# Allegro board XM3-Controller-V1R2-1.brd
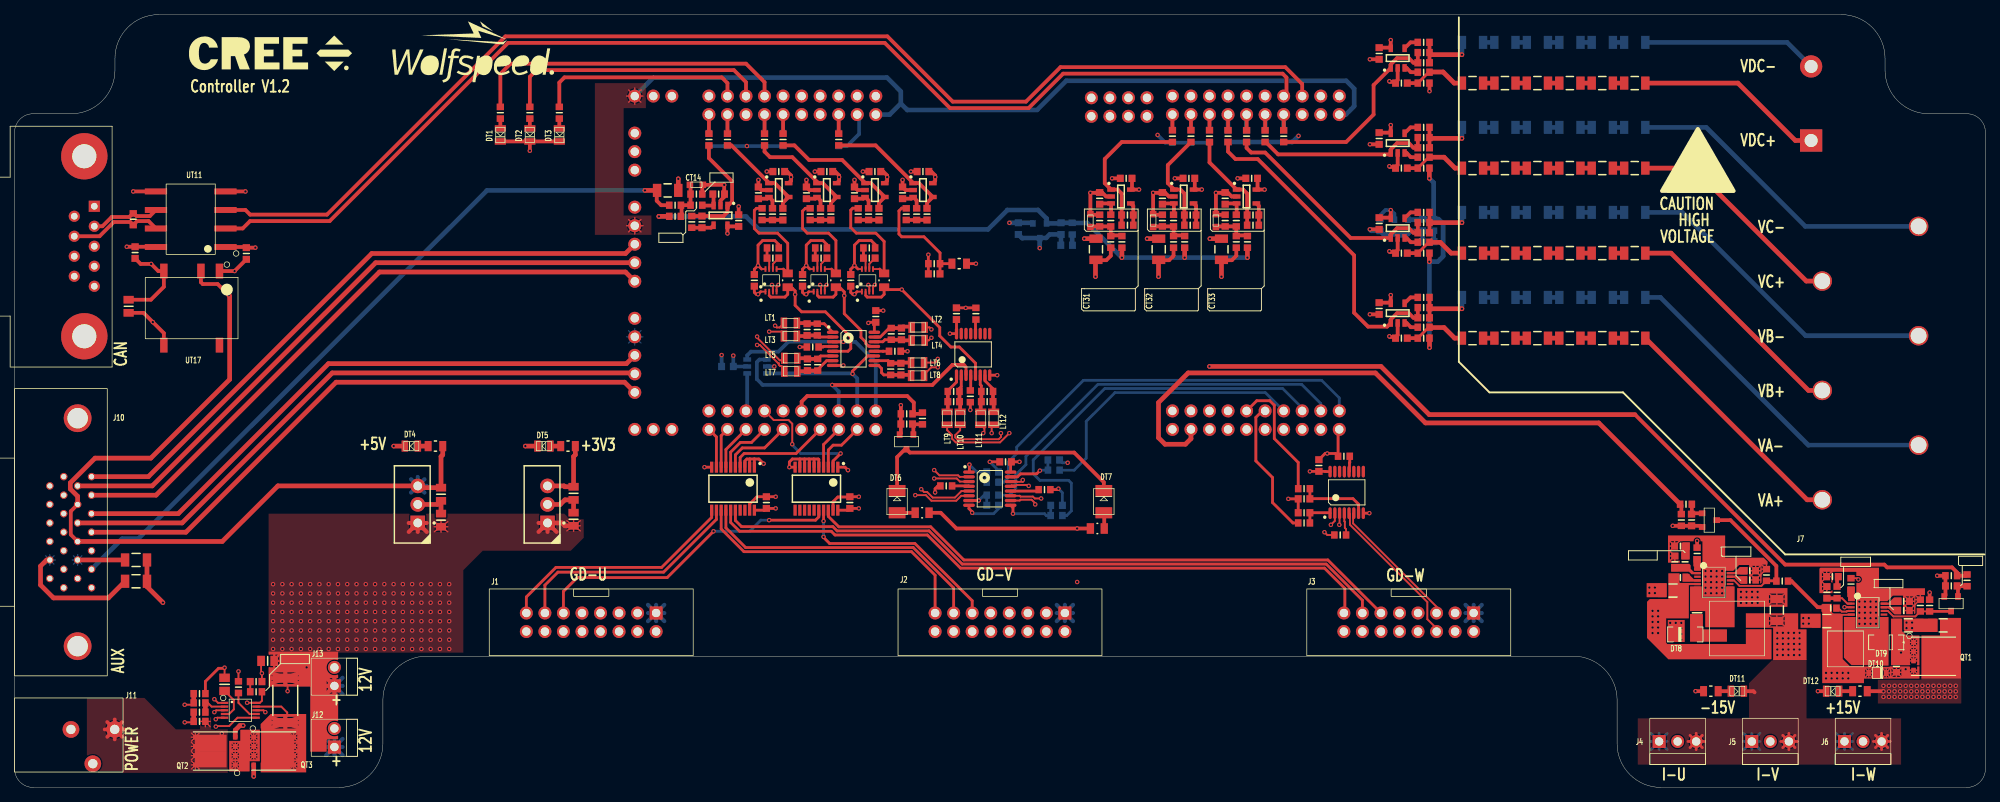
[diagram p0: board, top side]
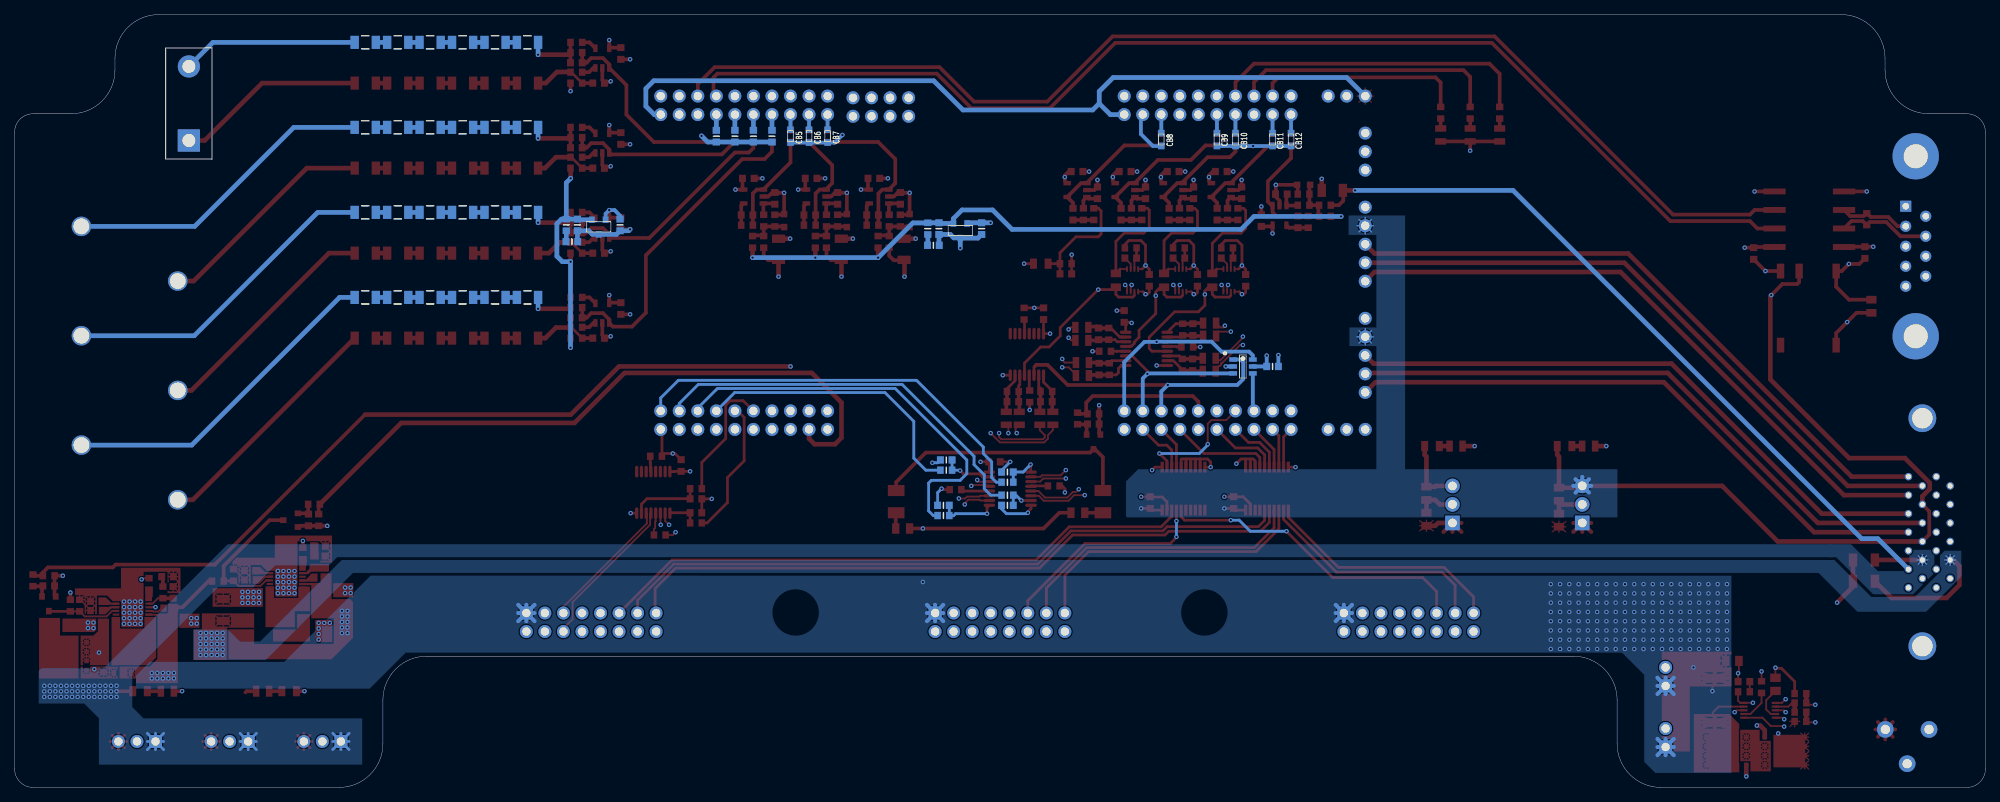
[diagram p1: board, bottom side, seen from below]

Outline 270 x 106 mm; copper layers: TOP, GND1, LAYER3, PWR, GND2, BOTTOM. Coordinates in mm from the lower left corner of the outline.
Outline path: 0,89.86 0,2.54 arc(0.74,0.74) 2.54,0 44.46,0 arc(48.7,1.76) 50.46,6 50.46,12 arc(52.21,16.24) 56.46,18 213.54,18 arc(217.79,16.24) 219.54,12 219.54,6 arc(221.3,1.76) 225.54,0 267.46,0 arc(269.26,0.74) 270,2.54 270,89.86 arc(269.26,91.65) 267.46,92.4 262.25,92.4 arc(258.01,94.15) 256.25,98.4 256.25,100 arc(254.49,104.24) 250.25,106 19.75,106 arc(15.51,104.24) 13.75,100 13.75,98.4 arc(11.99,94.15) 7.75,92.4 2.54,92.4 arc(0.74,91.65) 0,89.86

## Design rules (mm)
constraint set DEFAULT: min track width 0.178
net group A-FAULT-: nets A-FAULT-N A-FAULT-P
net group A-RTD-: nets A-RTD-N A-RTD-P
net group AHS-PWM-: nets AHS-PWM-N AHS-PWM-P
net group ALS-PWM-: nets ALS-PWM-N ALS-PWM-P
net group B-FAULT-: nets B-FAULT-N B-FAULT-P
net group B-RTD-: nets B-RTD-N B-RTD-P
net group BHS-PWM-: nets BHS-PWM-N BHS-PWM-P
net group BLS-PWM-: nets BLS-PWM-N BLS-PWM-P
net group C-FAULT-: nets C-FAULT-N C-FAULT-P
net group C-RTD-: nets C-RTD-N C-RTD-P
net group CANA: nets CANA-H CANA-L
net group CANB: nets CANBH CANBL
net group CHS-PWM-: nets CHS-PWM-N CHS-PWM-P
net group CLS-PWM-: nets CLS-PWM-N CLS-PWM-P
net group VBM: nets N45813 N45817 N45821 N51246 N51250 VB-M

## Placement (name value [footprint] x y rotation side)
CB1  0.27 uF  [CAPC1608X90N]  173.86 89.32 270 bottom
CB2  0.27 uF  [CAPC1608X90N]  171.32 89.32 270 bottom
CB3  0.27 uF  [CAPC1608X90N]  168.78 89.32 270 bottom
CB4  0.27 uF  [CAPC1608X90N]  166.24 89.32 270 bottom
CB5  4700pF  [C_0603]  163.7 89.32 270 bottom
CB6  4700pF  [C_0603]  161.16 89.32 270 bottom
CB7  4700pF  [C_0603]  158.62 89.32 270 bottom
CB8  4700pF  [C_0603]  112.9 88.86 270 bottom
CB9  4700pF  [C_0603]  105.28 88.86 270 bottom
CB10  4700pF  [C_0603]  102.74 88.86 270 bottom
CB11  4700pF  [C_0603]  97.66 88.86 270 bottom
CB12  4700pF  [C_0603]  95.12 88.86 270 bottom
CB13  10000pF  [CAPC1608X90N]  192.89 77.15 270 bottom
CB14  -  [CAPC1608X87N]  187.05 77.15 270 bottom
CB15  10000pF  [CAPC1608X90N]  143.36 76.64 270 bottom
CB16  -  [CAPC1608X87N]  137.52 76.64 270 bottom
CB17  10uF  [CAPC1608X90N]  193.65 74.86 180 bottom
CB18  10uF  [CAPC1608X90N]  144.12 74.35 180 bottom
CB19  -  [CAPC1608X87N]  97.66 57.74 180 bottom
CB20  100pF  [CAPC1608X90N]  142.37 44.91 0 bottom
CB21  100pF  [CAPC1608X90N]  133.98 43.26 0 bottom
CB22  100pF  [CAPC1608X90N]  142.75 38.69 0 bottom
CB23  100pF  [CAPC1608X90N]  133.98 38.69 0 bottom
CT1  -  [CAPC1608X87N]  186.94 100.66 270 top
CT2  4700pF  [CAPC1608X90N]  193.04 99.39 180 top
CT3  4700pF  [CAPC1608X90N]  189.99 96.6 0 top
CT4  -  [CAPC1608X87N]  186.94 89 270 top
CT5  10000pF  [CAPC1608X90N]  193.04 87.73 180 top
CT6  10000pF  [CAPC1608X90N]  189.99 84.94 0 top
CT7  -  [CAPC1608X87N]  104.69 84.47 180 top
CT8  -  [CAPC1608X87N]  111.28 84.47 180 top
CT9  -  [CAPC1608X87N]  117.86 84.47 180 top
CT10  -  [CAPC1608X87N]  124.44 84.47 180 top
CT11  -  [CAPC1608X87N]  152.28 83.53 180 top
CT12  -  [CAPC1608X87N]  160.88 83.53 180 top
CT13  -  [CAPC1608X87N]  169.48 83.53 180 top
CT14  4700pF  [C_0603]  93.41 82.65 0 top
CT15  10000pF  [CAPC1608X90N]  101.9 81.55 270 top
CT16  10000pF  [CAPC1608X90N]  108.48 81.55 270 top
CT17  10000pF  [CAPC1608X90N]  115.07 81.55 270 top
CT18  4700pF  [CAPC1608X90N]  121.65 81.55 270 top
CT19  100pF  [CAPC1608X90N]  96.46 81.38 0 top
CT20  100pF  [CAPC1608X90N]  148.65 80.79 90 top
CT21  100pF  [CAPC1608X90N]  157.25 80.79 90 top
CT22  100pF  [CAPC1608X90N]  165.85 80.79 90 top
CT23  10000pF  [CAPC1608X90N]  105.25 78.63 90 top
CT24  10000pF  [CAPC1608X90N]  111.83 78.63 90 top
CT25  10000pF  [CAPC1608X90N]  118.42 78.63 90 top
CT26  10000pF  [CAPC1608X90N]  125 78.63 90 top
CT27  100pF  [CAPC1608X90N]  152.46 78.51 180 top
CT28  100pF  [CAPC1608X90N]  161.06 78.51 180 top
CT29  100pF  [CAPC1608X90N]  169.66 78.51 180 top
CT30  -  [CAPC1608X87N]  99.2 77.74 90 top
CT31  4700pF  [C_0603]  147.38 77.74 90 top
CT32  4700pF  [C_0603]  155.98 77.74 90 top
CT33  4700pF  [C_0603]  164.58 77.74 90 top
CT34  100pF  [CAPC1608X90N]  94.17 77.57 90 top
CT35  -  [CAPC1608X87N]  186.94 77.34 270 top
CT36  10000pF  [CAPC1608X90N]  193.04 76.07 180 top
CT37  -  [CAPC1608X87N]  16.51 73.36 270 top
CT38  10000pF  [CAPC1608X90N]  189.99 73.28 0 top
CT39  -  [CAPC1608X87N]  31.75 73.23 270 top
CT40  10000pF  [CAPC1608X90N]  103.88 72.6 0 top
CT41  10000pF  [CAPC1608X90N]  110.49 72.6 0 top
CT42  10000pF  [CAPC1608X90N]  117.09 72.6 0 top
CT43  100pF  [CAPC1608X90N]  125.98 70.44 0 top
CT44  -  [CAPC1608X87N]  101.34 69.55 270 top
CT45  -  [CAPC1608X87N]  107.95 69.55 270 top
CT46  -  [CAPC1608X87N]  114.55 69.55 270 top
CT47  10uF  [CAPC2012X135N]  15.62 65.99 90 top
CT48  -  [CAPC1608X87N]  186.94 65.68 270 top
CT49  -  [CAPC1608X87N]  129.03 64.98 90 top
CT50  -  [CAPC1608X87N]  117.98 64.59 90 top
CT51  10000pF  [CAPC1608X90N]  193.04 64.41 180 top
CT52  27pF  [CAPC1608X90N]  108.57 62.8 90 top
CT53  27pF  [CAPC1608X90N]  121.5 62.2 90 top
CT54  10000pF  [CAPC1608X90N]  189.99 61.62 0 top
CT55  27pF  [CAPC1608X90N]  108.62 57.97 270 top
CT56  27pF  [CAPC1608X90N]  121.42 57.38 270 top
CT57  27pF  [CAPC1608X90N]  128.65 52.91 180 top
CT58  27pF  [CAPC1608X90N]  133.24 52.91 0 top
CT59  100pF  [CAPC1608X90N]  122.22 49.84 180 top
CT60  -  [CAPC1608X87N]  135.76 44.66 180 top
CT61  -  [CAPC1608X87N]  178.69 44.15 90 top
CT62  10uF  [CAPC2012X135N]  76.58 40.34 270 top
CT63  10uF  [CAPC2012X135N]  58.42 40.21 270 top
CT64  100pF  [CAPC1608X90N]  176.66 39.58 180 top
CT65  -  [CAPC1608X87N]  103 39.07 90 top
CT66  -  [CAPC1608X87N]  114.43 39.07 90 top
CT67  100pF  [CAPC1608X90N]  176.66 37.67 180 top
CT68  10uF  [CAPC2012X135N]  76.58 36.78 90 top
CT69  100pF  [CAPC1608X90N]  229.74 36.68 270 top
CT70  10uF  [CAPC2012X135N]  58.42 36.65 90 top
CT71  1000pF  [CAPC1608X90N]  228.22 33.1 180 top
CT72  10 uF  [CAPC3216X180N]  16.64 31.19 0 top
CT73  56 pF  [CAPC1608X90N]  227.46 30.94 270 top
CT74  0.1uF  [CAPC1608X90N]  237.72 29.72 180 top
CT75  1000pF  [CAPC1608X90N]  249.05 28.91 180 top
CT76  10 uF  [CAPC3216X180N]  16.64 28.27 0 top
CT77  100pF  [CAPC1608X90N]  265.33 27.64 180 top
CT78  4.7uF  [CAPC3216X180N]  227.2 27 180 top
CT79  56 pF  [CAPC1608X90N]  248.28 26.75 270 top
CT80  0.1uF  [CAPC1608X90N]  258.8 25.53 180 top
CT81  10 uF  [CAPC3216X180N]  241.43 24.34 90 top
CT82  1uF  [CAPC2012X70N]  230.5 23.95 270 top
CT83  4.7uF  [CAPC3216X180N]  248.28 22.81 180 top
CT84  4.7uF  [CAPC3216X180N]  259.43 22.23 0 top
CT85  10 uF  [CAPC3216X180N]  264.21 22.23 180 top
CT86  10uF  [CAPC2012X135N]  34.67 17.35 180 top
CT87  4700pF  [CAPC1608X90N]  33.08 14.51 0 top
CT88  0.022uF  [CAPC2012X70N]  28.76 14.13 90 top
DT1  LH R974-LP-1  [D_0805]  66.55 89.49 270 top
DT2  LTST-C171KSKT  [D_0805]  70.59 89.49 270 top
DT3  LG R971-KN-1  [D_0805]  74.63 89.49 270 top
DT4  LTST-C171GKT  [D_0805]  54.35 46.81 180 top
DT5  LTST-C171GKT  [D_0805]  72.52 46.81 180 top
DT6  AA3528VRVFS/A  [D_1409]  120.9 37.67 90 top
DT7  AA3528VRVFS/A  [D_1409]  149.22 37.67 90 top
DT8  NTS260ESFT3G  [SOD-123F-AC]  228.88 20.98 180 top
DT9  NTS260ESFT3G  [SOD-123F-AC]  256.41 19.89 360 top
DT10  CUS520,H3F  [SOD-323-AC]  255.14 15.7 0 top
DT11  LTST-C171GKT  [D_0805]  236.02 13.2 0 top
DT12  LTST-C171GKT  [D_0805]  249.07 13.2 180 top
J1  SBH11-PBPC-D08-ST-BK  [CON_2X8_SHROUDED_CORRECTED]  87.89 23.92 270 top
J2  SBH11-PBPC-D08-ST-BK  [CON_2X8_SHROUDED_CORRECTED]  143.89 23.92 270 top
J3  SBH11-PBPC-D08-ST-BK  [CON_2X8_SHROUDED_CORRECTED]  199.89 23.92 270 top
J4  0022232031  [CON_1X3_VERT_LOCK]  225.3 6.3 90 top
J5  0022232031  [CON_1X3_VERT_LOCK]  238 6.3 90 top
J6  0022232031  [CON_1X3_VERT_LOCK]  250.7 6.3 90 top
J7  1719231  [PHOENIX_SPT5_6PIN]  247.65 39.45 90 top
J8  CON2  [2POS_400MIL_TERMINAL]  246.12 88.72 90 bottom
J9  A-DS 09 A/KG-T2S  [DB9]  10.92 79.71 90 top
J10  10226-55G3PC  [MDR-26]  6.73 27.38 270 top
J11  PJ-102AH  [POWERJACK-PJ102AH]  13.71 7.95 270 top
J12  640456-2  [CON_1X2_VERT_LOCK]  43.81 5.54 180 top
J13  640456-2  [CON_1X2_VERT_LOCK]  43.81 13.92 180 top
LT1  1uH  [L_0805]  106.29 63.68 0 top
LT2  1uH  [L_0805]  123.79 63.09 180 top
LT3  1uH  [L_0805]  106.29 61.91 0 top
LT4  1uH  [L_0805]  123.79 61.31 180 top
LT5  1uH  [L_0805]  106.34 58.86 0 top
LT6  1uH  [L_0805]  123.71 58.27 180 top
LT7  1uH  [L_0805]  106.34 57.08 0 top
LT8  1uH  [L_0805]  123.71 56.49 180 top
LT9  1uH  [L_0805]  127.76 50.62 90 top
LT10  1uH  [L_0805]  129.54 50.62 90 top
LT11  1uH  [L_0805]  132.35 50.62 90 top
LT12  1uH  [L_0805]  134.13 50.62 90 top
LT13  6.8u  [IND-MSD7342]  235.96 21.8 180 top
LT14  3.3uH  [IND-5040]  250.82 19 0 top
NOREF  -  [unnamed]  19.91 17.77 0 top
NOREF#2  -  [unnamed]  107 23.99 0 top
NOREF#3  -  [#2]  27.62 0 90 top
NOREF#4  -  [#2]  225.42 81.51 0 top
NOREF#5  -  [unnamed]  135 99.7 0 top
NOREF#6  -  [unnamed]  19.91 99.7 0 top
NOREF#7  -  [unnamed]  264 86.4 0 top
NOREF#8  -  [unnamed]  264 6 0 top
NOREF#9  -  [#2]  23.87 96.6 0 top
NOREF#10  -  [unnamed]  163 23.99 0 top
NOREF#11  -  [#2]  0 87.23 0 top
QT1  SI7461DP  [POWER-SO8]  262.89 17.99 0 top
QT2  DMT6005LPS-13  [POWER-SO8]  27.49 4.99 180 top
QT3  DMT6005LPS-13  [POWER-SO8]  35.5 4.99 0 top
RB1  249 kOhm  [RESC3216X65N]  221.96 102.19 180 bottom
RB2  249 kOhm  [RESC3216X65N]  217.51 102.19 180 bottom
RB3  249 kOhm  [RESC3216X65N]  213.07 102.19 180 bottom
RB4  249 kOhm  [RESC3216X65N]  208.62 102.19 180 bottom
RB5  249 kOhm  [RESC3216X65N]  204.18 102.19 180 bottom
RB6  249 kOhm  [RESC3216X65N]  199.73 102.19 180 bottom
RB7  249 kOhm  [RESC3216X65N]  221.96 90.53 180 bottom
RB8  249 kOhm  [RESC3216X65N]  217.51 90.53 180 bottom
RB9  249 kOhm  [RESC3216X65N]  213.07 90.53 180 bottom
RB10  249 kOhm  [RESC3216X65N]  208.62 90.53 180 bottom
RB11  249 kOhm  [RESC3216X65N]  204.18 90.53 180 bottom
RB12  249 kOhm  [RESC3216X65N]  199.73 90.53 180 bottom
RB13  249 kOhm  [RESC3216X65N]  221.96 78.87 180 bottom
RB14  249 kOhm  [RESC3216X65N]  217.51 78.87 180 bottom
RB15  249 kOhm  [RESC3216X65N]  213.07 78.87 180 bottom
RB16  249 kOhm  [RESC3216X65N]  208.62 78.87 180 bottom
RB17  249 kOhm  [RESC3216X65N]  204.18 78.87 180 bottom
RB18  249 kOhm  [RESC3216X65N]  199.73 78.87 180 bottom
RB19  2k  [RESC1608X55N]  194.42 77.15 270 bottom
RB20  2k  [RESC1608X55N]  144.89 76.64 270 bottom
RB21  249 kOhm  [RESC3216X65N]  221.96 67.21 180 bottom
RB22  249 kOhm  [RESC3216X65N]  217.51 67.21 180 bottom
RB23  249 kOhm  [RESC3216X65N]  213.07 67.21 180 bottom
RB24  249 kOhm  [RESC3216X65N]  208.62 67.21 180 bottom
RB25  249 kOhm  [RESC3216X65N]  204.18 67.21 180 bottom
RB26  249 kOhm  [RESC3216X65N]  199.73 67.21 180 bottom
RB27  120  [RESC1608X55N]  142.37 43.51 180 bottom
RB28  120  [RESC1608X55N]  133.98 41.86 180 bottom
RB29  120  [RESC1608X55N]  133.98 40.08 180 bottom
RB30  120  [RESC1608X55N]  142.75 37.29 180 bottom
RT1  4.99k  [RESC1608X55N]  193.04 102.19 180 top
RT2  3.74 k  [RESC1608X55N]  193.04 100.79 180 top
RT3  4.99k  [RESC1608X55N]  193.04 98.1 180 top
RT4  3.74 k  [RESC1608X55N]  193.04 96.6 180 top
RT5  249 kOhm  [RESC3216X65N]  199.73 96.6 180 top
RT6  249 kOhm  [RESC3216X65N]  204.18 96.6 180 top
RT7  249 kOhm  [RESC3216X65N]  208.62 96.6 180 top
RT8  249 kOhm  [RESC3216X65N]  213.07 96.6 180 top
RT9  249 kOhm  [RESC3216X65N]  217.51 96.6 180 top
RT10  249 kOhm  [RESC3216X65N]  221.96 96.6 180 top
RT11  680  [RESC1608X55N]  66.55 92.53 270 top
RT12  680  [RESC1608X55N]  70.59 92.53 270 top
RT13  680  [RESC1608X55N]  74.63 92.53 270 top
RT14  4.99k  [RESC1608X55N]  193.04 90.53 180 top
RT15  49.9  [RESC1608X55N]  158.62 89.32 90 top
RT16  49.9  [RESC1608X55N]  161.16 89.32 90 top
RT17  49.9  [RESC1608X55N]  163.7 89.32 90 top
RT18  49.9  [RESC1608X55N]  166.24 89.32 90 top
RT19  49.9  [RESC1608X55N]  168.78 89.32 90 top
RT20  49.9  [RESC1608X55N]  171.32 89.32 90 top
RT21  49.9  [RESC1608X55N]  173.86 89.32 90 top
RT22  1.8 kOhm  [RESC1608X55N]  193.04 89.13 180 top
RT23  49.9  [RESC1608X55N]  95.12 88.86 90 top
RT24  49.9  [RESC1608X55N]  97.66 88.86 90 top
RT25  49.9  [RESC1608X55N]  102.74 88.86 90 top
RT26  49.9  [RESC1608X55N]  105.28 88.86 90 top
RT27  49.9  [RESC1608X55N]  112.9 88.86 90 top
RT28  4.99k  [RESC1608X55N]  193.04 86.44 180 top
RT29  1.8 kOhm  [RESC1608X55N]  193.04 84.94 180 top
RT30  249 kOhm  [RESC3216X65N]  199.73 84.94 180 top
RT31  249 kOhm  [RESC3216X65N]  204.18 84.94 180 top
RT32  249 kOhm  [RESC3216X65N]  208.62 84.94 180 top
RT33  249 kOhm  [RESC3216X65N]  213.07 84.94 180 top
RT34  249 kOhm  [RESC3216X65N]  217.51 84.94 180 top
RT35  249 kOhm  [RESC3216X65N]  221.96 84.94 180 top
RT36  27  [RESC3216X65N]  89.47 81.88 0 top
RT37  4.02 kOhm  [RESC1608X55N]  93.41 81.38 180 top
RT38  2k  [RESC1608X55N]  90.49 79.85 0 top
RT39  7.15 kOhm  [RESC1608X55N]  93.41 79.85 0 top
RT40  4.99k  [RESC1608X55N]  193.04 78.87 180 top
RT41  30.1k  [RESC1608X55N]  102.41 78.63 270 top
RT42  30.1k  [RESC1608X55N]  103.83 78.63 90 top
RT43  30.1k  [RESC1608X55N]  108.99 78.63 270 top
RT44  30.1k  [RESC1608X55N]  110.41 78.63 90 top
RT45  30.1k  [RESC1608X55N]  115.57 78.63 270 top
RT46  30.1k  [RESC1608X55N]  117 78.63 90 top
RT47  30.1k  [RESC1608X55N]  122.16 78.63 270 top
RT48  17.8k  [RESC1608X55N]  123.58 78.63 90 top
RT49  1.33 k  [RESC1608X55N]  90.49 78.33 0 top
RT50  120  [RESC1608X55N]  16.25 77.93 90 top
RT51  4.02 kOhm  [RESC1608X55N]  148.65 77.74 270 top
RT52  7.15 kOhm  [RESC1608X55N]  150.18 77.74 90 top
RT53  4.02 kOhm  [RESC1608X55N]  157.25 77.74 270 top
RT54  7.15 kOhm  [RESC1608X55N]  158.77 77.74 90 top
RT55  4.02 kOhm  [RESC1608X55N]  165.85 77.74 270 top
RT56  7.15 kOhm  [RESC1608X55N]  167.37 77.74 90 top
RT57  7.87 kOhm  [RESC1608X55N]  92.77 77.57 90 top
RT58  1.8 kOhm  [RESC1608X55N]  193.04 77.47 180 top
RT59  7.87 kOhm  [RESC1608X55N]  152.46 77.11 180 top
RT60  7.87 kOhm  [RESC1608X55N]  161.06 77.11 180 top
RT61  7.87 kOhm  [RESC1608X55N]  169.66 77.11 180 top
RT62  2k  [RESC1608X55N]  150.18 74.82 90 top
RT63  1.33 k  [RESC1608X55N]  151.7 74.82 90 top
RT64  2k  [RESC1608X55N]  158.77 74.82 90 top
RT65  1.33 k  [RESC1608X55N]  160.3 74.82 90 top
RT66  2k  [RESC1608X55N]  167.37 74.82 90 top
RT67  1.33 k  [RESC1608X55N]  168.9 74.82 90 top
RT68  4.99k  [RESC1608X55N]  193.04 74.78 180 top
RT69  2.2k  [RESC1608X55N]  103.88 73.99 180 top
RT70  2.2k  [RESC1608X55N]  110.49 73.99 180 top
RT71  2.2k  [RESC1608X55N]  117.09 73.99 180 top
RT72  27  [RESC3216X65N]  148.14 73.81 90 top
RT73  27  [RESC3216X65N]  156.74 73.81 90 top
RT74  27  [RESC3216X65N]  165.34 73.81 90 top
RT75  1.8 kOhm  [RESC1608X55N]  193.04 73.28 180 top
RT76  249 kOhm  [RESC3216X65N]  199.73 73.28 180 top
RT77  249 kOhm  [RESC3216X65N]  204.18 73.28 180 top
RT78  249 kOhm  [RESC3216X65N]  208.62 73.28 180 top
RT79  249 kOhm  [RESC3216X65N]  213.07 73.28 180 top
RT80  249 kOhm  [RESC3216X65N]  217.51 73.28 180 top
RT81  249 kOhm  [RESC3216X65N]  221.96 73.28 180 top
RT82  10k  [RESC1608X65N]  125.98 71.83 0 top
RT83  10 kOhm  [RESC2012X60N]  129.41 71.83 0 top
RT84  0  [RESC2012X70N]  105.92 69.55 90 top
RT85  0  [RESC2012X70N]  112.52 69.55 90 top
RT86  0  [RESC2012X70N]  119.12 69.55 90 top
RT87  4.99k  [RESC1608X55N]  193.04 67.21 180 top
RT88  1.8 kOhm  [RESC1608X55N]  193.04 65.81 180 top
RT89  15k  [RESC1608X55N]  131.7 64.97 90 top
RT90  4.99k  [RESC1608X55N]  193.04 63.12 180 top
RT91  100  [RESC1608X55N]  109.97 62.8 90 top
RT92  100  [RESC1608X55N]  120.1 62.2 90 top
RT93  1.8 kOhm  [RESC1608X55N]  193.04 61.62 180 top
RT94  249 kOhm  [RESC3216X65N]  199.73 61.62 180 top
RT95  249 kOhm  [RESC3216X65N]  204.18 61.62 180 top
RT96  249 kOhm  [RESC3216X65N]  208.62 61.62 180 top
RT97  249 kOhm  [RESC3216X65N]  213.07 61.62 180 top
RT98  249 kOhm  [RESC3216X65N]  217.51 61.62 180 top
RT99  249 kOhm  [RESC3216X65N]  221.96 61.62 180 top
RT100  15k  [RESC1608X55N]  109.35 60.4 0 top
RT101  15k  [RESC1608X55N]  120.6 59.82 0 top
RT102  100  [RESC1608X55N]  110.02 57.97 270 top
RT103  100  [RESC1608X55N]  120.03 57.38 270 top
RT104  100  [RESC1608X55N]  128.65 54.31 180 top
RT105  100  [RESC1608X55N]  133.24 54.31 0 top
RT106  15k  [RESC1608X55N]  130.94 53.64 90 top
RT107  10k  [RESC1608X65N]  122.22 51.24 180 top
RT108  120  [RESC1608X55N]  124.38 50.6 270 top
RT109  499  [RESC2012X60N]  57.66 46.81 180 top
RT110  249  [RESC2012X60N]  75.82 46.81 180 top
RT111  15k  [RESC1608X55N]  182.12 45.42 0 top
RT112  15k  [RESC1608X55N]  127.63 41.35 0 top
RT113  120  [RESC1608X55N]  176.66 40.97 0 top
RT114  15k  [RESC1608X55N]  141.1 40.85 180 top
RT115  120  [RESC1608X55N]  228.98 38.84 0 top
RT116  1.8k  [RESC2013X65N]  124.33 37.67 180 top
RT117  10k  [RESC1608X65N]  228.34 36.68 270 top
RT118  120  [RESC1608X55N]  176.66 36.27 0 top
RT119  1.8k  [RESC2013X65N]  148.33 35.51 0 top
RT120  15k  [RESC1608X55N]  181.61 34.62 0 top
RT121  180K  [RESC1608X55N]  230.5 32.08 90 top
RT122  10k  [RESC1608X65N]  228.85 30.94 90 top
RT123  10k  [RESC1608X65N]  240 29.14 90 top
RT124  10k  [RESC1608X65N]  265.33 29.03 180 top
RT125  100k  [RESC1608X55N]  228.22 28.78 0 top
RT126  45.3k  [RESC1608X55N]  237.72 28.45 180 top
RT127  120  [RESC1608X55N]  267.49 28.4 270 top
RT128  56k  [RESC1608X55N]  242.16 28.3 0 top
RT129  165k  [RESC1608X55N]  251.59 27.89 90 top
RT130  10k  [RESC1608X65N]  249.68 26.75 90 top
RT131  10k  [RESC1608X65N]  261.09 24.95 90 top
RT132  56k  [RESC1608X55N]  262.36 24.95 90 top
RT133  100k  [RESC1608X55N]  248.79 24.59 0 top
RT134  45.3k  [RESC1608X55N]  258.8 24.26 180 top
RT135  100k  [RESC1608X55N]  257.81 16.59 270 top
RT136  100k  [RESC1608X55N]  30.67 13.75 270 top
RT137  2.43k  [RESC2012X60N]  232.39 13.2 0 top
RT138  2.43k  [RESC2012X60N]  252.81 13.2 180 top
RT139  22k  [RESC1608X55N]  33.08 13.12 0 top
RT140  200k  [RESC1608X55N]  25.34 12.86 0 top
RT141  0.01  [RESC6432X70N]  37.08 11.93 90 top
RT142  100k  [RESC1608X55N]  25.34 11.59 180 top
RT143  2.7 M  [RESC1608X55N]  25.34 10.32 0 top
RT144  2.7 M  [RESC1608X55N]  25.34 9.05 180 top
UB1  ISL21080CIH315Z-TK  [SOT_23_3]  192.36 74.99 180 bottom
UB2  ISL21080CIH330Z-TK  [SOT_23_3]  142.83 74.48 180 bottom
UB3  SN74LVC1G11DBVR  [SOT_23_6]  103.06 58.69 270 bottom
UT1  AD8615AUJZ-REEL7  [SOT23-5_0_95X2_70P_H1_22]  189.48 100.03 90 top
UT2  AD8615AUJZ-REEL7  [SOT23-5_0_95X2_70P_H1_22]  189.48 88.37 90 top
UT3  AD8615AUJZ-REEL7  [SOT23-5_0_95X2_70P_H1_22]  104.69 81.93 0 top
UT4  AD8615AUJZ-REEL7  [SOT23-5_0_95X2_70P_H1_22]  111.28 81.93 0 top
UT5  AD8615AUJZ-REEL7  [SOT23-5_0_95X2_70P_H1_22]  117.86 81.93 0 top
UT6  AD8615AUJZ-REEL7  [SOT23-5_0_95X2_70P_H1_22]  124.44 81.93 0 top
UT7  AD8615AUJZ-REEL7  [SOT23-5_0_95X2_70P_H1_22]  151.57 81.05 0 top
UT8  AD8615AUJZ-REEL7  [SOT23-5_0_95X2_70P_H1_22]  160.17 81.05 0 top
UT9  AD8615AUJZ-REEL7  [SOT23-5_0_95X2_70P_H1_22]  168.77 81.05 0 top
UT10  AD8615AUJZ-REEL7  [SOT23-5_0_95X2_70P_H1_22]  96.71 78.45 270 top
UT11  ISO1050DUBR  [SMD-8_GULL_WING_V2]  28.89 74.12 180 top
UT12  AD8615AUJZ-REEL7  [SOT23-5_0_95X2_70P_H1_22]  189.48 76.71 90 top
UT13  F28379D-launchpad  [F28379D-LAUNCHPAD-1]  84.96 79.58 180 top
UT14  74LVC123  [VFSOP-8]  103.63 69.55 90 top
UT15  74LVC123  [VFSOP-8]  110.23 69.55 90 top
UT16  74LVC123  [VFSOP-8]  116.84 69.55 90 top
UT17  R1SE-0505-R  [8-SMD-5LEADS]  28.07 70.82 270 top
UT18  AD8615AUJZ-REEL7  [SOT23-5_0_95X2_70P_H1_22]  189.48 65.05 90 top
UT19  AM26LV32EIPWR  [TSSOP-16P_P65MM]  114.93 60.15 0 top
UT20  AM26LV32EIPWR  [TSSOP-16P_P65MM]  131.32 59.39 90 top
UT21  BSS138L  [SOT_23_3]  119.8 45.52 0 top
UT22  SN74LV541ATPWR  [SOP65P640X120-20AN]  98.42 40.97 270 top
UT23  SN74LV541ATPWR  [SOP65P640X120-20AN]  109.85 40.97 270 top
UT24  AM26LV31EIPWR  [TSSOP-16P_P65MM]  133.6 40.97 0 top
UT25  AM26LV31EIPWR  [TSSOP-16P_P65MM]  182.5 40.46 90 top
UT26  R-78E5.0-1.0  [TO-220V]  55.23 38.81 90 top
UT27  R-78E3.3-1.0  [TO-220V]  73.01 38.81 90 top
UT28  BSS138L  [SOT_23_3]  234.06 34.27 90 top
UT29  LT3581  [MSOP-16-EP]  232.79 28.15 0 top
UT30  BSS138L  [SOT_23_3]  262.91 23.32 0 top
UT31  LT3581  [MSOP-16-EP]  253.87 23.95 0 top
UT32  LTC4368IMS-2#PBF  [MSOP_10]  28.76 11.59 0 top

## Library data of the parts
CB1-CB13 CB15 CB17 CB18 CB20-CB23 CT2 CT3 CT5 CT6 CT14-CT29 CT31-CT34 CT36 CT38 CT40-CT43 CT47 CT51-CT59 CT62-CT64 CT67-CT88 = CAP
CB14 CB16 CB19 CT1 CT4 CT7-CT13 CT30 CT35 CT37 CT39 CT44-CT46 CT48-CT50 CT60 CT61 CT65 CT66 = CAP_CAPC1608X87N_DISCRETE_0.1UF
DT1-DT5 DT11 DT12 = LED_0
DT6 DT7 = LED - Purple
DT8 DT9 = DIODE_SCHOTTKY_0
DT10 = DIODE_SCHOTTKY_C2_A1_0
J1-J3 = CON16A_Corrected
J4-J6 = CON3
J7 = HDR_1X6_M
J8 = CON2
J9 = DSUB - NI CAN Interface_0: User Part Number: TMP-1302
J10 = CONN CENT RCPT 26
J11 = power_jack
J12 J13 = 1x2 100mil
LT1-LT12 = INDUCTOR
LT13 = Coupled_Inductor
LT14 = IND
QT1 = MOSFET_P_PSO8: User Part Number: TMP-1595; Tolerance: TOL
QT2 QT3 = MOSFET_N_PSO8: User Part Number: TMP-1530; Tolerance: TOL
RB1-RB26 RT1-RT36 RT38 RT40-RT48 RT58 RT62 RT64 RT66 RT68-RT81 RT84-RT88 RT90-RT99 RT102-RT105 RT126 RT129 RT134 RT141 = RES
RB27-RB30 RT37 RT39 RT49-RT57 RT59-RT61 RT63 RT65 RT67 RT82 RT89 RT100 RT101 RT106-RT125 RT127 RT128 RT130-RT133 RT135-RT140 RT142-RT144 = R
RT83 = PTC
UB1 UB2 = REF3312AIDCKR - Vref_0
UB3 = AND3_1X_6PIN
UT1-UT10 UT12 UT18 = AD8615
UT11 = ISO1050DUB
UT13 = F28379D-launchpad
UT14-UT16 = 74LVC123
UT17 = R1se-0505-R
UT19 UT20 = DIFFRCVR_4XG_16P
UT21 UT28 UT30 = MOSFET_N_GSD
UT22 UT23 = 74-541_20P
UT24 UT25 = DIFFDRVR_4X_16P
UT26 UT27 = LM7805
UT29 UT31 = LT3581
UT32 = LTC4368

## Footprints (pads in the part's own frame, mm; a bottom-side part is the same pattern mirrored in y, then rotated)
2POS_400MIL_TERMINAL
  rect 3.048x3.048 hole 1.778: 1(0,0)
  round 3.048 hole 1.778: 2(10.16,0)
8-SMD-5LEADS
  rect 2.032x1.016 smd: 1(0,0) 2(0,-2.54) 4(0,-7.62) 5(10.16,-7.62) 8(10.16,0)
C_0603
  rect 0.889x0.889 smd: 1(-0.889,0) 2(0.889,0)
CAPC1608X87N
  rect 0.95x1 smd: 1(-0.8,0) 2(0.8,0)
CAPC1608X90N
  rect 0.95x1 smd: 1(-0.8,0) 2(0.8,0)
CAPC2012X70N
  rect 1.15x1.45 smd: 1(-0.9,0) 2(0.9,0)
CAPC2012X135N
  rect 1.05x1.4 smd: 1(-0.9,0) 2(0.9,0)
CAPC3216X180N
  rect 1.15x1.8 smd: 1(-1.5,0) 2(1.5,0)
CON_1X2_VERT_LOCK
  rect 1.778x1.778 hole 1.143: 1(0,0)
  round 1.778 hole 1.143: 2(0,-2.54)
CON_1X3_VERT_LOCK
  rect 1.778x1.778 hole 1.143: 1(0,0)
  round 1.778 hole 1.143: 2(0,-2.54) 3(0,-5.08)
CON_2X8_SHROUDED_CORRECTED
  rect 1.778x1.778 hole 1.143: 1(0,0)
  round 1.778 hole 1.143: 2(2.54,0) 3(0,-2.54) 4(2.54,-2.54) 5(0,-5.08) 6(2.54,-5.08) 7(0,-7.62) 8(2.54,-7.62) 9(0,-10.16) 10(2.54,-10.16) 11(0,-12.7) 12(2.54,-12.7) 13(0,-15.24) 14(2.54,-15.24) 15(0,-17.78) 16(2.54,-17.78)
D_0805
  rect 0.889x1.524 smd: 1(-0.889,0) 2(0.889,0)
D_1409
  rect 1.524x2.286 smd: 1(0,0) 2(3.048,0)
DB9
  rect 1.524x1.524 hole 0.914: 1(0,0)
  round 1.524 hole 0.914: 2(-2.743,0) 3(-5.486,0) 4(-8.23,0) 5(-10.973,0) 6(-1.372,2.743) 7(-4.115,2.743) 8(-6.858,2.743) 9(-9.601,2.743)
  round 6.35 hole 3.302: 10(6.858,1.372) 11(-17.831,1.372)
F28379D-LAUNCHPAD-1
  round 1.778 hole 1.143: 1(-96.52,-15.24) 2(-93.98,-15.24) 3(-91.44,-15.24) 4(-88.9,-15.24) 5(-86.36,-15.24) 6(-83.82,-15.24) 7(-81.28,-15.24) 8(-78.74,-15.24) 9(-76.2,-15.24) 10(-73.66,-15.24) 11(-73.66,30.48) 12(-76.2,30.48) 13(-78.74,30.48) 14(-81.28,30.48) 15(-83.82,30.48) 16(-86.36,30.48) 17(-88.9,30.48) 18(-91.44,30.48) 19(-93.98,30.48) 20(-96.52,30.48) 21(-96.52,-12.7) 22(-93.98,-12.7) 23(-91.44,-12.7) 24(-88.9,-12.7) 25(-86.36,-12.7) 26(-83.82,-12.7) 27(-81.28,-12.7) 28(-78.74,-12.7) 29(-76.2,-12.7) 30(-73.66,-12.7) 31(-73.66,27.94) 32(-76.2,27.94) 33(-78.74,27.94) 34(-81.28,27.94) 35(-83.82,27.94) 36(-86.36,27.94) 37(-88.9,27.94) 38(-91.44,27.94) 39(-93.98,27.94) 40(-96.52,27.94) 41(-33.02,-15.24) 42(-30.48,-15.24) 43(-27.94,-15.24) 44(-25.4,-15.24) 45(-22.86,-15.24) 46(-20.32,-15.24) 47(-17.78,-15.24) 48(-15.24,-15.24) 49(-12.7,-15.24) 50(-10.16,-15.24) 51(-10.16,30.48) 52(-12.7,30.48) 53(-15.24,30.48) 54(-17.78,30.48) 55(-20.32,30.48) 56(-22.86,30.48) 57(-25.4,30.48) 58(-27.94,30.48) 59(-30.48,30.48) 60(-33.02,30.48) 61(-33.02,-12.7) 62(-30.48,-12.7) 63(-27.94,-12.7) 64(-25.4,-12.7) 65(-22.86,-12.7) 66(-20.32,-12.7) 67(-17.78,-12.7) 68(-15.24,-12.7) 69(-12.7,-12.7) 70(-10.16,-12.7) 71(-10.16,27.94) 72(-12.7,27.94) 73(-15.24,27.94) 74(-17.78,27.94) 75(-20.32,27.94) 76(-22.86,27.94) 77(-25.4,27.94) 78(-27.94,27.94) 79(-30.48,27.94) 80(-33.02,27.94) 81(-70.176,-12.466) 82(-70.176,-15.006) 83(-67.636,-12.466) 84(-67.636,-15.006) 85(-65.096,-12.466) 86(-65.096,-15.006) 87(-62.556,-12.466) 88(-62.556,-15.006) 89(0,25.4) 90(0,22.86) 91(0,20.32) 92(0,17.78) 93(0,15.24) 94(0,10.16) 95(0,7.62) 96(0,5.08) 97(0,2.54) 98(0,0) 99(0,-5.08) 100(0,-7.62) 101(0,-10.16) 102(0,30.48) 103(-2.54,30.48) 104(-5.08,30.48) 105(0,-15.24) 106(-2.54,-15.24) 107(-5.08,-15.24)
IND-5040
  rect 1.5x4 smd: 1(-1.8,0) 2(1.8,0)
IND-MSD7342
  rect 2.35x1.1 smd: 1(-2.825,0.85) 2(-2.825,-0.85) 3(2.825,-0.85) 4(2.825,0.85)
L_0805
  rect 0.889x1.524 smd: 1(-0.889,0) 2(0.889,0)
MDR-26
  round 3.81 hole 2.794: (-23.254,1.905) (8.014,1.905)
  round 1.016 hole 0.711: 1(0,0) 2(0,3.81) 3(-1.27,-1.905) 4(-1.27,1.905) 5(-2.54,0) 6(-2.54,3.81) 7(-3.81,-1.905) 8(-3.81,1.905) 9(-5.08,0) 10(-5.08,3.81) 11(-6.35,-1.905) 12(-6.35,1.905) 13(-7.62,0) 14(-7.62,3.81) 15(-8.89,-1.905) 16(-8.89,1.905) 17(-10.16,0) 18(-10.16,3.81) 19(-11.43,-1.905) 20(-11.43,1.905) 21(-12.7,0) 22(-12.7,3.81) 23(-13.97,-1.905) 24(-13.97,1.905) 25(-15.24,0) 26(-15.24,3.81)
MSOP-16-EP
  rect 0.9x0.3 smd: 1(-2.235,1.751) 2(-2.235,1.251) 3(-2.235,0.751) 4(-2.235,0.25) 5(-2.235,-0.25) 6(-2.235,-0.751) 7(-2.235,-1.251) 8(-2.235,-1.751) 9(2.235,-1.751) 10(2.235,-1.251) 11(2.235,-0.751) 12(2.235,-0.25) 13(2.235,0.25) 14(2.235,0.751) 15(2.235,1.251) 16(2.235,1.751)
  rect 1.651x3.048 smd: 17(0,0)
MSOP_10
  rect 1.016x0.305 smd: 1(0,0) 2(0,-0.508) 3(0,-1.016) 4(0,-1.524) 5(0,-2.032) 6(4.318,-2.032) 7(4.318,-1.524) 8(4.318,-1.016) 9(4.318,-0.508) 10(4.318,0)
PHOENIX_SPT5_6PIN
  round 2.667 hole 2.159: 1(0,0) 2(7.5,-13.2) 3(15,0) 4(22.5,-13.2) 5(30,0) 6(37.5,-13.2)
POWER-SO8
  rect 0.63x0.65 smd: 1(-2.735,1.905) 2(-2.735,0.635) 3(-2.735,-0.635) 4(-2.735,-1.905) 5(2.735,-1.905) 6(2.735,-0.635) 7(2.735,0.635) 8(2.735,1.905)
POWERJACK-PJ102AH
  round 2.286 hole 1.27: 1(0,0) 2(0,-5.994) 3(4.699,-2.997)
RESC1608X55N
  rect 0.9x1 smd: 1(-0.8,0) 2(0.8,0)
RESC1608X65N
  rect 0.9x1 smd: 1(-0.8,0) 2(0.8,0)
RESC2012X60N
  rect 0.95x1.4 smd: 1(-1,0) 2(1,0)
RESC2012X70N
  rect 1.05x1.4 smd: 1(-0.95,0) 2(0.95,0)
RESC2013X65N
  rect 1x1.45 smd: 1(-0.95,0) 2(0.95,0)
RESC3216X65N
  rect 1.15x1.8 smd: 1(-1.45,0) 2(1.45,0)
RESC6432X70N
  rect 1.25x3.4 smd: 1(-3.05,0) 2(3.05,0)
SMD-8_GULL_WING_V2
  rect 3.048x0.813 smd: 1(0,0) 2(0,-2.54) 3(0,-5.08) 4(0,-7.62) 5(9.525,-7.62) 6(9.525,-5.08) 7(9.525,-2.54) 8(9.525,0)
SOD-123F-AC
  rect 0.914x1.27 smd: 1(1.651,0) 2(-1.651,0)
SOD-323-AC
  rect 0.635x0.838 smd: A(-1.118,0) C(1.27,0)
SOP65P640X120-20AN
  rect 1.5x0.45 smd: 1(-2.95,2.925) 2(-2.95,2.275) 3(-2.95,1.625) 4(-2.95,0.975) 5(-2.95,0.325) 6(-2.95,-0.325) 7(-2.95,-0.975) 8(-2.95,-1.625) 9(-2.95,-2.275) 10(-2.95,-2.925) 11(2.95,-2.925) 12(2.95,-2.275) 13(2.95,-1.625) 14(2.95,-0.975) 15(2.95,-0.325) 16(2.95,0.325) 17(2.95,0.975) 18(2.95,1.625) 19(2.95,2.275) 20(2.95,2.925)
SOT23-5_0_95X2_70P_H1_22
  rect 1.05x0.6 smd: 1(-1.35,0.95) 2(-1.35,0) 3(-1.35,-0.95) 4(1.35,-0.95) 5(1.35,0.95)
SOT_23_3
  rect 0.787x0.889 smd: 1(3.327,2.87) 2(1.448,2.87) 3(2.388,0.864)
SOT_23_6
  rect 0.61x1.067 smd: 1(0,0) 2(0.953,0) 3(1.905,0) 4(1.905,2.692) 5(0.953,2.692) 6(0,2.692)
TO-220V
  rect 2x2 hole 1.2: 1(-2.54,0)
  round 2 hole 1.2: 2(0,0) 3(2.54,0)
TSSOP-16P_P65MM
  oval 1.6x0.45 smd: 1(-2.85,2.275) 2(-2.85,1.625) 3(-2.85,0.975) 4(-2.85,0.325) 5(-2.85,-0.325) 6(-2.85,-0.975) 7(-2.85,-1.625) 8(-2.85,-2.275) 9(2.85,-2.275) 10(2.85,-1.625) 11(2.85,-0.975) 12(2.85,-0.325) 13(2.85,0.325) 14(2.85,0.975) 15(2.85,1.625) 16(2.85,2.275)
unnamed
  round 0 hole 4.318 unplated: (0,0)
VFSOP-8
  rect 0.762x0.254 smd: 1(-1.549,0.762) 2(-1.549,0.254) 3(-1.549,-0.254) 4(-1.549,-0.762) 5(1.549,-0.762) 6(1.549,-0.254) 7(1.549,0.254) 8(1.549,0.762)

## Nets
+1V5REF: CB13.1 RB19.1 RT29.1 RT75.1 RT93.1 UB1.2(OUT)
+3V3: CB14.1 CB16.1 CB19.1 CT1.1 CT4.1 CT7.1 CT8.1 CT9.1 CT10.1 CT11.1 CT12.1 CT13.1 CT30.1 CT35.1 CT39.1 CT44.1 CT45.1 CT46.1 CT48.1 CT49.1 CT50.1 CT60.1 CT61.1 CT62.1 J10.10 RT69.1 RT70.1 RT71.1 RT83.2 RT100.1 RT106.1 RT110.1 RT112.1 RT120.1 UB1.1 UB2.1 UB3.5 UT1.5 UT2.5 UT3.5 UT4.5 UT5.5 UT6.5 UT7.5 UT8.5 UT9.5 UT10.5 UT11.1 UT12.5 UT13.1 UT13.41 UT13.102 UT14.3 UT14.8(VCC) UT15.3 UT15.8(VCC) UT16.3 UT16.8(VCC) UT18.5 UT19.16 UT20.16 UT24.16 UT25.16 UT27.3(OUTPUT)
+3VREF: CB15.1 RB20.1 RT49.1 RT63.1 RT65.1 RT67.1 UB2.2(OUT)
+5V: CT63.1 CT65.1 CT66.1 J10.12 J10.20 RT109.1 UT13.21 UT13.61 UT13.92 UT13.97 UT13.105 UT17.2 UT22.20 UT23.20 UT26.3(OUTPUT)
+5V-ISO: CT37.1 CT47.1 J9.9 UT11.8(VCC2) UT17.5
+12V: CT68.1 CT70.1 CT78.1 CT83.1 CT86.1 DT10.A J1.1 J2.1 J3.1 J12.1 J13.1 LT13.1 LT14.1 RT116.1 RT119.1 RT125.1 RT128.2 RT132.2 RT133.1 RT141.2 UT26.1 UT27.1 UT29.5 UT31.5 UT32.8(VOUT)
+15V: CT72.1 CT85.1 J4.1 J5.1 J6.1 J10.8 QT1.5 QT1.6 QT1.7 QT1.8 RT138.1
-15V: CT76.1 CT81.1 DT11.2(C) J4.3 J5.3 J6.3 J10.7 LT13.2 RT121.2
VIN: J11.1(VIN) QT2.5 QT2.6 QT2.7 QT2.8 RT136.1 RT144.1 UT32.1
0: CB1.2 CB2.2 CB3.2 CB4.2 CB5.2 CB6.2 CB7.2 CB8.2 CB9.2 CB10.2 CB11.2 CB12.2 CB13.2 CB14.2 CB15.2 CB16.2 CB17.2 CB18.2 CB19.2 CB20.2 CB21.2 CB22.2 CB23.2 CT1.2 CT3.1 CT4.2 CT6.1 CT7.2 CT8.2 CT9.2 CT10.2 CT11.2 CT12.2 CT13.2 CT14.2 CT15.1 CT16.1 CT17.1 CT18.1 CT19.2 CT20.2 CT21.2 CT22.2 CT30.2 CT31.2 CT32.2 CT33.2 CT35.2 CT38.1 CT39.2 CT43.1 CT44.2 CT45.2 CT46.2 CT48.2 CT49.2 CT50.2 CT54.1 CT59.2 CT60.2 CT61.2 CT62.2 CT63.2 CT64.2 CT65.2 CT66.2 CT67.2 CT68.2 CT69.2 CT70.2 CT71.2 CT72.2 CT73.1 CT74.1 CT75.2 CT76.2 CT77.2 CT78.2 CT79.1 CT80.1 CT81.2 CT83.2 CT84.2 CT85.2 CT86.2 CT87.2 CT88.2 DT1.2(C) DT2.2(C) DT3.2(C) DT4.2(C) DT5.2(C) DT8.1(C) DT12.2(C) J1.2 J1.12 J1.14 J1.16 J2.2 J2.12 J2.14 J2.16 J3.2 J3.12 J3.14 J3.16 J10.3 J10.4 J10.5 J10.9 J10.11 J10.13 J10.15 J10.17 J10.19 J10.21 J10.23 J10.25 J11.2 J11.3 J12.2 J13.2 RT4.1 RT36.2 RT37.1 RT51.1 RT53.1 RT55.1 RT72.2 RT73.2 RT74.2 RT82.1 RT89.2 RT101.2 RT107.2 RT111.1 RT114.1 RT117.2 RT123.2 RT124.2 RT126.1 RT131.2 RT134.1 RT137.1 RT140.2 UB1.3 UB2.3 UB3.2 UT1.2(V-) UT2.2(V-) UT3.2(V-) UT4.2(V-) UT5.2(V-) UT6.2(V-) UT7.2(V-) UT8.2(V-) UT9.2(V-) UT10.2(V-) UT11.4 UT12.2(V-) UT13.20 UT13.22 UT13.60 UT13.62 UT13.82 UT13.84 UT13.86 UT13.88 UT13.93 UT13.98 UT13.101 UT13.103 UT13.104 UT13.106 UT13.107(GND15) UT14.1 UT14.4 UT15.1 UT15.4 UT16.1 UT16.4 UT17.1 UT18.2(V-) UT19.8 UT20.8 UT21.2(S) UT22.1 UT22.2 UT22.3 UT22.10 UT22.19 UT23.1 UT23.5 UT23.6 UT23.7 UT23.8 UT23.9 UT23.10 UT23.19 UT24.8 UT25.8 UT26.2 UT27.2 UT28.2(S) UT29.16 UT29.17 UT30.2(S) UT31.16 UT31.17 UT32.5
1: CT37.2 CT47.2 J9.3(V-) J9.5 J9.10 J9.11 UT11.5 UT17.4
A-CURRENT: CB7.1 RT15.2 UT13.30
A-FAULT: UB3.6 UT13.80 UT19.3
A-FAULT-N: J1.8 LT1.1
A-FAULT-N-FILTER: CT52.2 LT1.2 RT91.2 UT19.1
A-FAULT-P: J1.7 LT3.1
A-FAULT-P-FILTER: CT52.1 LT3.2 RT91.1 UT19.2
A-LEN: J1.13 UT22.12
A-LEN-OUT: UT13.52 UT22.8
A-OCEN: J1.15 UT22.11(Y8)
A-OCEN-OUT: UT13.51 UT22.9
A-PSDIS: J1.11 UT23.16
A-PSDIS-OUT: UT13.58 UT23.4
A-RTD: RT84.1 UT13.46 UT14.2 UT19.5
A-RTD-N: J1.10 LT7.1
A-RTD-N-FILTER: CT55.2 LT7.2 RT102.2 UT19.7
A-RTD-P: J1.9 LT5.1
A-RTD-P-FILTER: CT55.1 LT5.2 RT102.1 UT19.6
A-TEMP: CB11.1 RT24.2 UT13.69
AHS-PWM: RB28.1 UT13.40
AHS-PWM-N: J1.4 UT24.3
AHS-PWM-P: J1.3 UT24.2
ALS-PWM: RB29.1 UT13.39
ALS-PWM-N: J1.6 UT24.5
ALS-PWM-P: J1.5 UT24.6
B-CURRENT: CB6.1 RT16.2 UT13.29
B-FAULT: UB3.3 UT13.79 UT19.11
B-FAULT-N: J2.8 LT8.1
B-FAULT-N-FILTER: CT56.2 LT8.2 RT103.2 UT19.9
B-FAULT-P: J2.7 LT6.1
B-FAULT-P-FILTER: CT56.1 LT6.2 RT103.1 UT19.10
B-LEN: J2.13 UT22.14
B-LEN-OUT: UT13.54 UT22.6
B-OCEN: J2.15 UT22.13
B-OCEN-OUT: UT13.53 UT22.7
B-PSDIS: J2.11 UT23.17
B-PSDIS-OUT: UT13.59 UT23.3
B-RTD: RT85.1 UT13.45 UT15.2 UT19.13(Y4)
B-RTD-N: J2.10 LT2.1
B-RTD-N-FILTER: CT53.2 LT2.2 RT92.2 UT19.15
B-RTD-P: J2.9 LT4.1
B-RTD-P-FILTER: CT53.1 LT4.2 RT92.1 UT19.14
B-TEMP: CB10.1 RT25.2 UT13.67
BHS-PWM: RB30.1 UT13.38
BHS-PWM-N: J2.4 UT24.11
BHS-PWM-P: J2.3 UT24.10
BLS-PWM: RB27.1 UT13.37
BLS-PWM-N: J2.6 UT24.13(Z4)
BLS-PWM-P: J2.5 UT24.14
C-CURRENT: CB5.1 RT17.2 UT13.28
C-FAULT: UB3.1 UT13.78 UT20.3
C-FAULT-N: J3.8 LT9.1
C-FAULT-N-FILTER: CT57.2 LT9.2 RT104.2 UT20.1
C-FAULT-P: J3.7 LT10.1
C-FAULT-P-FILTER: CT57.1 LT10.2 RT104.1 UT20.2
C-LEN: J3.13 UT22.16
C-LEN-OUT: UT13.57 UT22.4
C-OCEN: J3.15 UT22.15
C-OCEN-OUT: UT13.55 UT22.5
C-PSDIS: J3.11 UT23.18
C-PSDIS-OUT: UT13.74 UT23.2
C-RTD: RT86.1 UT13.42 UT16.2 UT20.5
C-RTD-N: J3.10 LT12.1
C-RTD-N-FILTER: CT58.2 LT12.2 RT105.2 UT20.7
C-RTD-P: J3.9 LT11.1
C-RTD-P-FILTER: CT58.1 LT11.2 RT105.1 UT20.6
C-TEMP: CB9.1 RT26.2 UT13.66
CANA-H: J9.7 RT50.1 UT11.7
CANA-L: J9.2 RT50.2 UT11.6
CANA-RX: UT11.2 UT13.4
CANA-TX: UT11.3 UT13.3
CANBH: J10.2 UT13.99
CANBL: J10.1 UT13.100
CASE-LED1: RT107.1 RT108.1 UT13.76
CASE-LED2: UT13.75
CASE-TEMP: CB8.1 RT27.2 UT13.63
CHS-PWM: RT118.1 UT13.36
CHS-PWM-N: J3.4 UT25.3
CHS-PWM-P: J3.3 UT25.2
CLS-PWM: RT113.1 UT13.35
CLS-PWM-N: J3.6 UT25.5
CLS-PWM-P: J3.5 UT25.6
EXT-CURRENT: CB12.1 RT23.2 UT13.70
GLOBAL-FAULT: UB3.4(Y) UT13.73
IA-M: J4.2 RT62.1 RT72.1
IB-M: J5.2 RT64.1 RT73.1
IC-M: J6.2 RT66.1 RT74.1
IEXT-M: J10.6 RT36.1 RT38.1
LED-G: RT13.1 UT13.49
LED-R: RT11.1 UT13.47
LED-Y: RT12.1 UT13.48
QEA_A: J10.14 UT13.89
QEA_B: J10.16 UT13.90
QEA_I: J10.18 UT13.91
QEB_A: J10.22 UT13.94
QEB_B: J10.24 UT13.95
QEB_I: J10.26 UT13.96
SHUTDOWN+15V: RT124.1 RT127.1 UT13.13
SHUTDOWN-15V: RT115.1 RT117.1 UT13.12
VA-M: J7.2 RB21.1
VA-P: J7.1 RT99.1
VB-M: J7.4 RB13.1
VB-P: J7.3 RT81.1
VC-M: J7.6(PIN6) RB7.1
VC-P: J7.5 RT35.1
VDC-M: J8.2 RB1.1
VDC-P: J8.1 RT10.1
VSENSE-A: CB4.1 RT18.2 UT13.27
VSENSE-B: CB3.1 RT19.2 UT13.26
VSENSE-C: CB2.1 RT20.2 UT13.25
VSENSE-DC: CB1.1 RT21.2 UT13.24
N07282: RT100.2 UT19.4
N07299: RT101.1 UT19.12
N07508: RT106.2 UT20.4
N07516: RT89.1 UT20.12
N07693: RT112.2 UT24.4
N07878: RT120.2 UT25.4
N09835: CB21.1 RB28.2 UT24.1
N10049: CB23.1 RB29.2 UT24.7
N10085: CB22.1 RB30.2 UT24.9
N10121: CB20.1 RB27.2 UT24.15
N11382: RT114.2 UT24.12
N11987: RT111.2 UT25.12
N12714: CT67.1 RT118.2 UT25.1
N12754: CT64.1 RT113.2 UT25.7
N16187: CT23.2 RT24.1 UT3.1 UT3.4
N16636: CT23.1 RT41.2 RT42.1
N16643: CT15.2 RT42.2 UT3.3
N18013: CT24.1 RT43.2 RT44.1
N18021: CT24.2 RT25.1 UT4.1 UT4.4
N18093: CT16.2 RT44.2 UT4.3
N18488: CT25.1 RT45.2 RT46.1
N18496: CT25.2 RT26.1 UT5.1 UT5.4
N18568: CT17.2 RT46.2 UT5.3
N28683: CT27.2 RT15.1 RT59.2 UT7.1
N28695: CT27.1 RT59.1 UT7.4
N28775: CT20.1 RT52.2 UT7.3
N28956: CT31.1 RT51.2 RT52.1 RT62.2 RT63.2
N31299: CT32.1 RT53.2 RT54.1 RT64.2 RT65.2
N31469: CT21.1 RT54.2 UT8.3
N31505: CT28.2 RT16.1 RT60.2 UT8.1
N31529: CT28.1 RT60.1 UT8.4
N32358: CT33.1 RT55.2 RT56.1 RT66.2 RT67.2
N32528: CT22.1 RT56.2 UT9.3
N32564: CT29.2 RT17.1 RT61.2 UT9.1
N32588: CT29.1 RT61.1 UT9.4
N35636: RB23.2 RB24.1
N35646: RB24.2 RB25.1
N35650: RB25.2 RB26.1
N35794: RT96.1 RT97.2
N35798: RT95.1 RT96.2
N35802: RT94.1 RT95.2
N35806: CT54.2 RT90.1 RT93.2 RT94.2
N45499: RT78.1 RT79.2
N45503: RT77.1 RT78.2
N45507: RT76.1 RT77.2
N45511: CT38.2 RT68.1 RT75.2 RT76.2
N45813: RB15.2 RB16.1
N45817: RB16.2 RB17.1
N45821: RB17.2 RB18.1
N45825: CT36.1 RB18.2 RT40.1 RT58.1
N47166: RT32.1 RT33.2
N47170: RT31.1 RT32.2
N47174: RT30.1 RT31.2
N47178: CT6.2 RT28.1 RT29.2 RT30.2
N47480: RB9.2 RB10.1
N47484: RB10.2 RB11.1
N47488: RB11.2 RB12.1
N47492: CT5.1 RB12.2 RT14.1 RT22.1
N51028: RT98.1 RT99.2
N51064: RB21.2 RB22.1
N51070: RT97.1 RT98.2
N51074: RB22.2 RB23.1
N51202: RT80.1 RT81.2
N51206: RT79.1 RT80.2
N51246: RB13.2 RB14.1
N51250: RB14.2 RB15.1
N51378: RT34.1 RT35.2
N51382: RT33.1 RT34.2
N51422: RB7.2 RB8.1
N51426: RB8.2 RB9.1
N62914: CT14.1 RT37.2 RT38.2 RT39.1 RT49.2
N63160: CT19.1 RT39.2 UT10.3
N63220: CT34.2 RT23.1 RT57.2 UT10.1
N63260: CT34.1 RT57.1 UT10.4
N66752: CT51.2 RT18.1 RT88.2 UT18.1
N66907: CT51.1 RB26.2 RT87.1 RT88.1
N66989: RT87.2 UT18.4
N67029: RT90.2 UT18.3
N74358: RT68.2 UT12.3
N74448: CT36.2 RT19.1 RT58.2 UT12.1
N74460: RT40.2 UT12.4
N75234: RT28.2 UT2.3
N75324: CT5.2 RT20.1 RT22.2 UT2.1
N75336: RT14.2 UT2.4
N76078: CT3.2 RT3.1 RT4.2 RT5.2
N76134: RT3.2 UT1.3
N76224: CT2.2 RT2.2 RT21.1 UT1.1
N76236: RT1.2 UT1.4
N76260: CT2.1 RB6.2 RT1.1 RT2.1
N78650: CT26.1 RT47.2 RT48.1
N78658: CT26.2 RT27.1 UT6.1 UT6.4
N78724: CT18.2 RT48.2 UT6.3
N79088: CT43.2 RT47.1 RT82.2 RT83.1
N88263: DT5.1 RT110.2
N88433: DT4.1 RT109.2
N88603: DT12.1 RT138.2
N88777: DT11.1 RT137.2
N93191: DT1.1 RT11.2
N93195: DT3.1 RT13.2
N93199: DT2.1 RT12.2
N95779: RT123.1 RT128.1 UT28.3 UT29.13(~SHDN)
N96795: RT131.1 RT132.1 UT30.3 UT31.13(~SHDN)
N97055: CT84.1 DT9.1(C) QT1.1 QT1.2 QT1.3(S2) RT129.2 RT135.1
N97211: CT79.2 RT130.1 UT31.2
N97283: CT75.1 RT130.2
N139937: RT9.1 RT10.2
N139941: RT8.1 RT9.2
N139945: RT7.1 RT8.2
N139949: RT6.1 RT7.2
N139953: RT5.1 RT6.2
N140053: RB1.2 RB2.1
N140057: RB2.2 RB3.1
N140061: RB3.2 RB4.1
N140065: RB4.2 RB5.1
N140069: RB5.2 RB6.1
N141814: CB17.1 RB19.2
N143941: CB18.1 RB20.2
N145779: CT69.1 RT115.2 UT28.1
N146352: CT77.1 RT127.2 UT30.1
N147166: QT2.1 QT2.2 QT2.3(S2) QT3.1 QT3.2 QT3.3(S2)
N148075: QT2.4 QT3.4 RT139.2 UT32.10
N148197: CT87.1 RT139.1
N148540: QT3.5 QT3.6 QT3.7 QT3.8 RT141.1 UT32.9
N149103: RT143.1 RT144.2 UT32.6
N149107: RT142.1 RT143.2 UT32.2
N149113: RT140.1 RT142.2 UT32.3
N149983: CT88.1 UT32.4
N150621: RT136.2 UT32.7
N177905: DT7.1 RT119.2
N177925: DT6.2(CATHODE) DT7.2(CATHODE) UT21.3
N178332: DT6.1 RT116.2
N179044: CT59.1 RT108.2 UT21.1
N200782: RT134.2 UT31.14
N203219: RT133.2 UT31.4
N204184: DT9.2 LT14.2 UT31.6 UT31.7 UT31.8 UT31.9 UT31.10 UT31.11
N204300: RT129.1 UT31.1
N204715: CT80.2 UT31.15
N205443: DT10.C(CATHODE) QT1.4 RT135.2 UT31.3
N208883: CT82.1 LT13.3 UT29.6 UT29.7 UT29.8 UT29.9 UT29.10 UT29.11
N209249: RT121.1 UT29.1
N209309: RT125.2 UT29.4
N209373: RT126.2 UT29.14
N209381: CT73.2 RT122.1 UT29.2
N209421: CT74.2 UT29.15
N209493: CT71.1 RT122.2
N213371: CT82.2 DT8.2 LT13.4
N273504: RT41.1 RT84.2 UT14.5
N273798: CT40.2 UT14.6
N273802: CT40.1 RT69.2 UT14.7
N275299: RT43.1 RT85.2 UT15.5
N275399: CT41.1 RT70.2 UT15.7
N275407: CT41.2 UT15.6
N275841: RT45.1 RT86.2 UT16.5
N275941: CT42.1 RT71.2 UT16.7
N275949: CT42.2 UT16.6

Pads without a net: J9 1 4 6 8; UT13 2 5 6 7 8 9 10 11 14 15 16 17 18 19 23 31 32 33 34 43 44 50 56 64 65 68 71 72 77 81 83 85 87; UT17 8; UT20 9 10 11 13 14 15; UT22 17 18; UT23 11 12 13 14 15; UT25 9 10 11 13 14 15; UT29 3 12; UT31 12

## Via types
v1: diameter 0.61, hole 0.33, TOP to BOTTOM, 503 vias

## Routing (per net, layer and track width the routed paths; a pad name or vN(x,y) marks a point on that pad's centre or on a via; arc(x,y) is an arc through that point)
+1V5REF: length 33.3
  TOP w0.635: RT93.1 v1(193.84,60.32) ; RT29.1 193.82,84.92 v1(193.82,83.54) ; v1(193.82,72.11) 193.82,73.26 RT75.1
  BOTTOM w0.635: RB19.1 194.42,82.94 v1(193.82,83.54) 193.84,83.56 ; RB19.1 CB13.1 192.8,77.86 UB1.2 ; RB19.1 195.07,77.95 195.71,77.31 195.71,72.85 194.96,72.11 v1(193.82,72.11) 193.84,72.08 v1(193.84,60.32)
+3V3: length 139.9
  TOP w0.254: UT14.3 103.88,68.79 v1(103.76,68.91) ; UT15.3 110.49,68.79 v1(110.36,68.91) ; UT15.8 108.94,71.1 ; v1(116.97,68.91) 117.09,68.79 UT16.3 ; UT14.8 102.34,71.1 ; UT16.8 115.54,71.1 ; RT120.1 179.83,34.62 v1(179.45,35)
  TOP w0.381: v1(177.46,43.35) CT61.1 179.56,43.35 179.59,43.31 UT25.16 ; v1(115.06,71.58) 115.06,74.37 115.7,75.01 117.35,75.01 117.89,74.46 RT71.1 ; v1(115.06,71.58) 114.55,71.07 CT46.1 ; v1(115.06,71.58) 115.54,71.1 ; RT106.1 v1(130.94,51.77) ; v1(137.67,44.66) CT60.1 136.45,44.55 UT24.16 ; 108.94,71.1 v1(108.46,71.58) ; v1(108.46,71.58) 107.95,71.07 CT45.1 ; v1(108.46,71.58) 108.46,74.37 109.09,75.01 110.74,75.01 111.29,74.46 RT70.1 ; RT69.1 104.69,74.46 104.14,75.01 102.49,75.01 101.85,74.37 v1(101.85,71.58) ; v1(128.14,62.24) UT20.16 129.04,64.16 CT49.1 ; v1(101.85,71.58) 101.34,71.07 CT44.1 ; v1(101.85,71.58) 102.34,71.1 ; v1(126.11,40.46) 126.11,40.97 126.49,41.35 RT112.1 ; UT19.16 117.78,63.6 CT50.1 117.05,63.79 v1(116.97,63.71) ; RT100.1 v1(107.57,60.4) ; RT83.2 v1(131.7,71.83)
  TOP w0.508: UT4.5 112.96,83.21 v1(112.96,83.71) 112.96,83.93 112.42,84.47 CT8.1 ; v1(188.53,102.5) UT1.5 188.45,101.46 CT1.1 ; CT35.1 188.45,78.14 UT12.5 v1(188.53,79.18) ; v1(171.24,82) UT9.5 170.28,82.16 CT13.1 ; v1(32.98,74.03) CT39.1 31.66,74.12 UT11.1 ; CT48.1 188.45,66.48 UT18.5 v1(188.53,67.52) ; CT7.1 105.84,84.47 106.37,83.93 v1(106.37,83.71) 106.37,83.21 UT3.5 ; CT12.1 161.68,82.16 UT8.5 v1(162.65,82) ; UT6.5 126.12,83.21 v1(126.12,83.71) 126.12,83.93 125.59,84.47 CT10.1 ; CT4.1 188.45,89.8 UT2.5 v1(188.53,90.84) ; CT11.1 153.08,82.16 UT7.5 v1(154.05,82) ; UT5.5 119.54,83.21 v1(119.54,83.71) 119.54,83.93 119,84.47 CT9.1 ; v1(97.66,75.98) UT10.5 97.82,76.94 CT30.1
  TOP w0.635: RT110.1 76.82,45.62 76.58,45.38 CT62.1 75.38,41.24 75.27,41.35 UT27.3
  PWR w0.178: UT13.41 117.98,95.89 ; UT13.41 118.79,94.02 ; UT13.41 119.05,94.82 ; UT13.41 117.18,94.02 ; UT13.41 118.79,95.63 ; UT13.41 116.91,94.82 ; UT13.41 117.98,93.75 ; UT13.41 117.18,95.63 ; UT13.102 85.77,49.91 ; UT13.102 84.96,50.17 ; UT13.102 84.96,48.03 ; UT13.102 84.16,48.3 ; UT13.102 84.16,49.91 ; UT13.102 86.03,49.1 ; UT13.102 83.89,49.1 ; UT13.102 85.77,48.3 ; UT13.1 182.29,95.63 ; UT13.1 180.68,95.63 ; UT13.1 182.29,94.02 ; UT13.1 180.68,94.02 ; UT13.1 181.48,93.75 ; UT13.1 180.41,94.82 ; UT13.1 181.48,95.89 ; UT13.1 182.55,94.82 ; 10.11,32.89 J10.10 ; J10.10 10.97,32.04 ; J10.10 10.11,32.04 ; J10.10 10.97,32.89
  PWR w0.559: UT27.3 73.01,42.53 ; UT27.3 73.9,42.24 ; UT27.3 72.13,40.47 ; UT27.3 71.83,41.35 ; UT27.3 74.19,41.35 ; UT27.3 73.9,40.47 ; UT27.3 72.13,42.24
  BOTTOM w0.508: UB1.1 189.03,78.68 v1(188.53,79.18) 187.81,79.18 187.05,78.43 CB14.1 ; v1(98.46,59.22) CB19.1 UB3.5
  BOTTOM w0.635: UB2.1 139.41,77.44 CB16.1 v1(136.29,77.44)
+3VREF: length 91.2
  TOP w0.635: RT63.1 v1(151.7,72.66) ; RT67.1 v1(168.9,72.66) ; RT65.1 v1(160.3,72.66) ; v1(88.26,78.31) 88.28,78.33 RT49.1
  BOTTOM w0.635: v1(88.26,78.31) 100.2,78.31 101.98,76.53 133.35,76.53 136.02,79.2 140.21,79.2 141.38,78.03 UB2.2 143.27,77.35 CB15.1 RB20.1 144.9,77.42 146.94,77.42 v1(151.7,72.66) v1(160.3,72.66) v1(168.9,72.66)
+5V: length 278.8
  TOP w0.178: UT13.97 85.8,77.88 ; UT13.97 83.84,77.04 ; UT13.97 84.12,77.88 ; UT13.97 86.08,77.04 ; UT13.97 85.8,76.2 ; UT13.97 84.12,76.2 ; UT13.97 84.96,78.16 ; UT13.97 84.96,75.92 ; 84.12,95.66 UT13.105 ; UT13.105 86.08,94.82 ; UT13.105 84.96,93.7 ; UT13.105 85.8,95.66 ; UT13.105 83.84,94.82 ; UT13.105 84.12,93.98 ; UT13.105 84.96,95.94 ; UT13.105 85.8,93.98
  TOP w0.381: UT22.20 102.75,38.02 CT65.1 v1(104.27,38.27) ; v1(115.66,38.27) CT66.1 114.18,38.02 UT23.20
  TOP w0.508: UT17.2 25.53,69.29 25.78,69.04 27.81,69.04 v1(29.34,67.52) ; 8.63,38.81 7.7,37.87 7.7,34.67 8.63,33.73
  TOP w0.635: 8.63,38.81 8.63,39.93 7.63,40.94 7.63,41.77 11.03,45.16 18.67,45.16 29.46,55.96 29.46,67.39 v1(29.34,67.52) ; 8.63,33.73 28.45,33.73 36.07,41.35 UT26.3 55.48,41.11 CT63.1 58.42,45.38 58.66,45.62 RT109.1
  BOTTOM w0.178: 83.84,61.8 UT13.92 ; UT13.92 86.08,61.8 ; UT13.92 84.12,60.96 ; UT13.92 84.12,62.64 ; UT13.92 84.96,62.92 ; UT13.92 85.8,60.96 ; UT13.92 84.96,60.68 ; UT13.92 85.8,62.64 ; UT13.97 84.96,78.16 ; UT13.97 86.08,77.04 ; UT13.97 85.8,76.2 ; UT13.97 85.8,77.88 ; UT13.97 84.12,77.88 ; UT13.97 83.84,77.04 ; UT13.97 84.12,76.2 ; UT13.97 84.96,75.92
  BOTTOM w0.559: UT26.3 56.15,40.43 ; UT26.3 54,41.35 ; UT26.3 56.15,42.27 ; UT26.3 55.23,42.58 ; UT26.3 54.31,42.27 ; UT26.3 54.31,40.43 ; UT26.3 56.46,41.35
  BOTTOM w0.635: 121.41,93.8 122.3,92.92 140.08,92.92 144.09,96.92 182.43,96.92 183.51,95.84 183.51,93.42 182.37,92.28 UT13.21 ; 121.41,93.8 119.89,92.28 UT13.61 ; 121.41,93.8 121.41,95.46 119.51,97.36 87.5,97.36 UT13.105
+5V-ISO: length 19.5
  TOP w0.508: UT11.8 19.33,74.16 CT37.1 v1(15.37,74.16) ; CT47.1 17.66,65.09 v1(18.94,63.82) 20.45,62.31 UT17.5 20.45,60.15
  PWR w0.178: J9.9 8.18,70.98 ; J9.9 7.51,69.44 ; J9.9 9.05,70.11 ; J9.9 7.3,70.11 ; J9.9 8.18,69.23 ; J9.9 8.85,69.44 ; J9.9 7.51,70.78 ; J9.9 8.85,70.78
+12V: length 183
  TOP w0.178: 254.02,15.05 DT10.A ; DT10.A 254.02,16.35 ; DT10.A 254.52,15.05 ; DT10.A 254.57,15.7 ; DT10.A 253.48,15.7 ; DT10.A 254.52,16.35 ; DT10.A 253.53,15.05 ; DT10.A 253.53,16.35 ; CT70.1 59.35,35.76 ; CT70.1 57.49,35.76 ; CT70.1 58.42,35 ; CT70.1 57.49,36.45 ; CT70.1 59.35,36.45 ; CT70.1 59.35,35.06 ; CT70.1 58.42,36.51 ; CT70.1 57.49,35.06 ; CT68.1 77.51,35.19 ; CT68.1 77.51,36.58 ; CT68.1 76.58,36.64 ; CT68.1 76.58,35.13 ; CT68.1 77.51,35.88 ; CT68.1 75.65,35.19 ; CT68.1 75.65,36.58
  TOP w0.254: v1(37.4,13.2) 37.4,14.09 ; v1(34.35,10.32) 34.1,10.58 UT32.8
  TOP w0.305: CT86.1 35.57,18.28 ; CT86.1 36.32,17.35 ; CT86.1 35.57,16.42 ; CT86.1 36.27,18.28 ; CT86.1 36.27,16.42
  TOP w0.508: RT132.2 v1(262.36,26.72) ; RT119.1 v1(145.57,35.51) 129.03,35.51 126.87,37.67 RT116.1 ; RT128.2 243.43,28.3 247.01,24.72 247.86,24.72 RT133.1
  TOP w0.559: 73.01,35.04 UT27.1 ; UT27.1 71.78,35.04 ; UT27.1 71.78,36.27 ; UT27.1 74.24,35.04 ; 42.7,12.8 J13.1 ; J13.1 43.81,15.04 ; J13.1 43.81,12.8 ; J13.1 42.7,15.04 ; J13.1 42.7,13.92 ; RT141.2 39.01,14.27 ; RT141.2 35.15,14.98 ; RT141.2 35.15,14.27 ; RT141.2 37.08,14.13 ; RT141.2 39.01,14.98 ; RT141.2 35.15,15.69 ; RT141.2 39.01,15.69 ; RT141.2 37.08,15.84 ; UT26.1 56.46,35.04 ; UT26.1 56.46,36.27 ; UT26.1 54,36.27 ; UT26.1 55.23,35.04 ; UT26.1 54,35.04
  TOP w0.635: CT68.1 75.38,35.88 74.99,36.27 UT27.1
  LAYER3 w0.254: v1(37.4,13.2) 37.1,13.2 34.35,10.45 v1(34.35,10.32)
  LAYER3 w0.508: v1(262.36,26.72) 262.36,16.94 260.35,14.94 251.23,14.94 v1(251.21,14.95) ; v1(145.57,35.51) v1(145.57,28.17)
  BOTTOM w0.559: J13.1 43.81,15.04 ; J13.1 42.7,13.92 ; J13.1 42.7,15.04 ; J13.1 42.7,12.8 ; J13.1 44.93,15.04 ; J13.1 43.81,12.8 ; J13.1 44.93,12.8 ; J13.1 44.93,13.92 ; 142.77,25.04 J2.1 ; J2.1 142.77,22.8 ; J2.1 143.89,22.8 ; J2.1 145.01,22.8 ; J2.1 143.89,25.04 ; J2.1 142.77,23.92 ; J2.1 145.01,25.04 ; J2.1 145.01,23.92 ; J1.1 87.89,25.04 ; J1.1 89.01,22.8 ; J1.1 87.89,22.8 ; J1.1 86.77,22.8 ; J1.1 86.77,23.92 ; J1.1 89.01,23.92 ; J1.1 89.01,25.04 ; J1.1 86.77,25.04 ; 42.7,4.42 J12.1 ; J12.1 43.81,4.42 ; J12.1 42.7,5.54 ; J12.1 44.93,5.54 ; J12.1 44.93,4.42 ; J12.1 42.7,6.66 ; J12.1 44.93,6.66 ; J12.1 43.81,6.66 ; 198.77,25.04 J3.1 ; J3.1 199.89,25.04 ; J3.1 201.01,25.04 ; J3.1 199.89,22.8 ; J3.1 198.77,22.8 ; J3.1 201.01,22.8 ; J3.1 198.77,23.92 ; J3.1 201.01,23.92
  vias: v1(35.41,27.88) v1(35.41,26.61) v1(35.41,25.34) v1(35.41,24.07) v1(35.41,22.8) v1(35.41,21.53) v1(35.41,20.26) v1(35.41,18.99) v1(36.68,27.88) v1(36.68,26.61) v1(36.68,25.34) v1(36.68,24.07) v1(36.68,22.8) v1(36.68,21.53) v1(36.68,20.26) v1(36.68,18.99) v1(37.95,27.88) v1(37.95,26.61) v1(37.95,25.34) v1(37.95,24.07) v1(37.95,22.8) v1(37.95,21.53) v1(37.95,20.26) v1(37.95,18.99) v1(39.22,27.88) v1(39.22,26.61) v1(39.22,25.34) v1(39.22,24.07) v1(39.22,22.8) v1(39.22,21.53) v1(39.22,20.26) v1(39.22,18.99) v1(40,16.46) v1(40.49,27.88) v1(40.49,26.61) v1(40.49,25.34) v1(40.49,24.07) v1(40.49,22.8) v1(40.49,21.53) v1(40.49,20.26) v1(40.49,18.99) v1(41.76,27.88) v1(41.76,26.61) v1(41.76,25.34) v1(41.76,24.07) v1(41.76,22.8) v1(41.76,21.53) v1(41.76,20.26) v1(41.76,18.99) v1(43.03,27.88) v1(43.03,26.61) v1(43.03,25.34) v1(43.03,24.07) v1(43.03,22.8) v1(43.03,21.53) v1(43.03,20.26) v1(43.03,18.99) v1(44.3,27.88) v1(44.3,26.61) v1(44.3,25.34) v1(44.3,24.07) v1(44.3,22.8) v1(44.3,21.53) v1(44.3,20.26) v1(44.3,18.99) v1(45.57,27.88) v1(45.57,26.61) v1(45.57,25.34) v1(45.57,24.07) v1(45.57,22.8) v1(45.57,21.53) v1(45.57,20.26) v1(45.57,18.99) v1(46.84,27.88) v1(46.84,26.61) v1(46.84,25.34) v1(46.84,24.07) v1(46.84,22.8) v1(46.84,21.53) v1(46.84,20.26) v1(46.84,18.99) v1(48.11,27.88) v1(48.11,26.61) v1(48.11,25.34) v1(48.11,24.07) v1(48.11,22.8) v1(48.11,21.53) v1(48.11,20.26) v1(48.11,18.99) v1(49.38,27.88) v1(49.38,26.61) v1(49.38,25.34) v1(49.38,24.07) v1(49.38,22.8) v1(49.38,21.53) v1(49.38,20.26) v1(49.38,18.99) v1(50.65,27.88) v1(50.65,26.61) v1(50.65,25.34) v1(50.65,24.07) v1(50.65,22.8) v1(50.65,21.53) v1(50.65,20.26) v1(50.65,18.99) v1(51.92,27.88) v1(51.92,26.61) v1(51.92,25.34) v1(51.92,24.07) v1(51.92,22.8) v1(51.92,21.53) v1(51.92,20.26) v1(51.92,18.99) v1(53.19,27.88) v1(53.19,26.61) v1(53.19,25.34) v1(53.19,24.07) v1(53.19,22.8) v1(53.19,21.53) v1(53.19,20.26) v1(53.19,18.99) v1(54.46,27.88) v1(54.46,26.61) v1(54.46,25.34) v1(54.46,24.07) v1(54.46,22.8) v1(54.46,21.53) v1(54.46,20.26) v1(54.46,18.99) v1(55.73,27.88) v1(55.73,26.61) v1(55.73,25.34) v1(55.73,24.07) v1(55.73,22.8) v1(55.73,21.53) v1(55.73,20.26) v1(55.73,18.99) v1(57,27.88) v1(57,26.61) v1(57,25.34) v1(57,24.07) v1(57,22.8) v1(57,21.53) v1(57,20.26) v1(57,18.99) v1(58.27,27.88) v1(58.27,26.61) v1(58.27,25.34) v1(58.27,24.07) v1(58.27,22.8) v1(58.27,21.53) v1(58.27,20.26) v1(58.27,18.99) v1(59.54,27.88) v1(59.54,26.61) v1(59.54,25.34) v1(59.54,24.07) v1(59.54,22.8) v1(59.54,21.53) v1(59.54,20.26) v1(59.54,18.99) v1(224.4,24.22) v1(224.4,23.46) v1(224.4,22.69) v1(224.4,21.93) v1(224.4,21.17) v1(225.16,24.22) v1(225.16,23.46) v1(225.16,22.69) v1(225.16,21.93) v1(225.16,21.17) v1(248.17,15.71) v1(248.17,14.95) v1(248.93,15.71) v1(248.93,14.95) v1(249.69,15.71) v1(249.69,14.95) v1(250.45,15.71) v1(250.45,14.95) v1(251.21,15.71)
+15V: length 47.3
  TOP w0.508: RT138.1 256.01,13.2 v1(256.03,13.18)
  TOP w0.635: 8.63,31.19 CT72.1
  BOTTOM w0.178: 8.06,30.62 8.63,31.19 ; 8.63,31.19 8.06,31.77 ; 8.63,31.19 9.21,30.62 ; 8.63,31.19 8.63,30.46 ; 8.63,31.19 8.63,31.93 ; 8.63,31.19 7.9,31.19 ; 8.63,31.19 9.21,31.77 ; 8.63,31.19 9.37,31.19
  BOTTOM w0.381: J6.1 250.7,7.42 ; J6.1 249.58,6.3 ; J6.1 249.58,7.42 ; J6.1 251.82,5.18 ; J6.1 250.7,5.18 ; J6.1 249.58,5.18 ; J6.1 251.82,7.42 ; J6.1 251.82,6.3 ; J4.1 226.42,5.18 ; J4.1 224.18,6.3 ; J4.1 226.42,7.42 ; J4.1 224.18,5.18 ; J4.1 225.3,7.42 ; J4.1 225.3,5.18 ; J4.1 226.42,6.3 ; J4.1 224.18,7.42 ; 236.88,6.3 J5.1 ; J5.1 236.88,5.18 ; J5.1 239.12,5.18 ; J5.1 236.88,7.42 ; J5.1 238,5.18 ; J5.1 239.12,6.3 ; J5.1 238,7.42 ; J5.1 239.12,7.42
  vias: v1(256.03,13.94) v1(256.03,12.42) v1(256.79,13.94) v1(256.79,13.18) v1(256.79,12.42) v1(257.55,13.94) v1(257.55,13.18) v1(257.55,12.42) v1(258.32,13.94) v1(258.32,13.18) v1(258.32,12.42) v1(259.08,13.94) v1(259.08,13.18) v1(259.08,12.42) v1(259.84,13.94) v1(259.84,13.18) v1(259.84,12.42) v1(260.6,13.94) v1(260.6,13.18) v1(260.6,12.42) v1(261.36,13.94) v1(261.36,13.18) v1(261.36,12.42) v1(262.13,13.94) v1(262.13,13.18) v1(262.13,12.42) v1(262.89,13.94) v1(262.89,13.18) v1(262.89,12.42) v1(263.65,13.94) v1(263.65,13.18) v1(263.65,12.42) v1(264.41,13.94) v1(264.41,13.18) v1(264.41,12.42) v1(265.17,13.94) v1(265.17,13.18) v1(265.17,12.42) v1(265.94,13.94) v1(265.94,13.18) v1(265.94,12.42)
